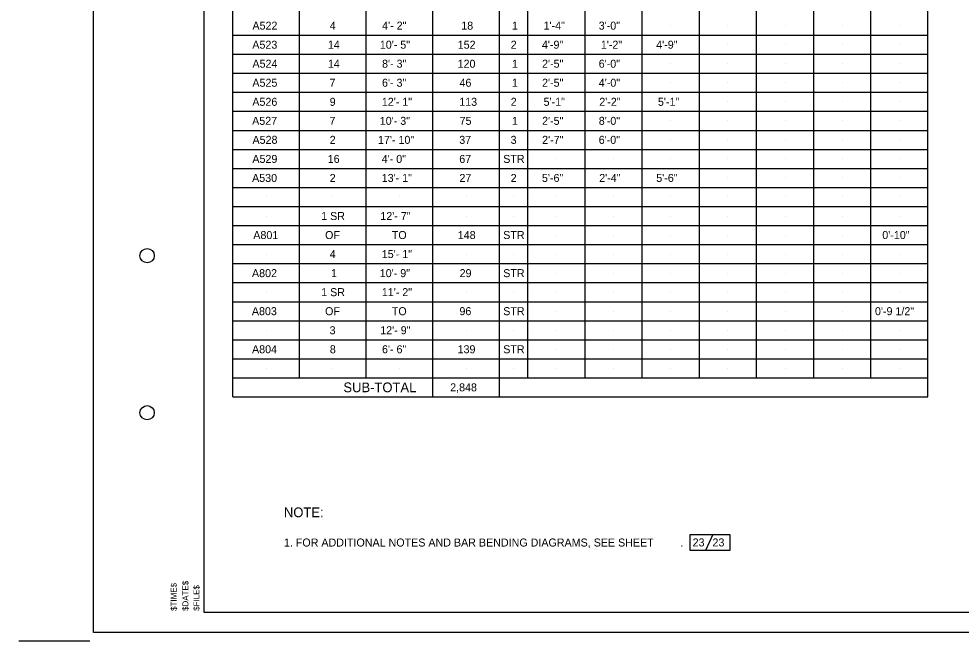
# Model space of a CAD drawing. Extents: x -9.2 to 26.7, y -0.9 to 21.1.
# Drawn here: x -9.21 to 7.28, y -0.89 to 10.01 of the extents above; entities that cross this region are included whole.
import ezdxf

# ---------------------------------------------------------------- set-up
doc = ezdxf.new("R2010")
doc.units = 0
for name, color, linetype in [('BR_P_Gen_Text', 7, 'Continuous'), ('Default', 7, 'Continuous'), ('SC_Scratch1', 7, 'Continuous'), ('SH_Border', 7, 'Continuous'), ('SH_Cut_Line', 7, 'Continuous'), ('TX_P_1', 7, 'Continuous')]:
    doc.layers.add(name, color=color, linetype=linetype)

msp = doc.modelspace()

# ---------------------------------------------------------------- linework, layer by layer
at = {"layer": 'BR_P_Gen_Text'}
for p, q in [((-5.469, 3.39), (-5.469, 20.207)), ((6.697, 3.39), (6.697, 20.207)), ((-4.302, 3.723), (-4.302, 18.39)), ((-3.135, 3.723), (-3.135, 18.39)), ((-1.969, 3.39), (-1.969, 18.39)), ((-0.802, 3.39), (-0.802, 18.39)), ((-0.302, 3.723), (-0.302, 18.39)), ((0.698, 3.723), (0.698, 18.39)), ((1.698, 3.723), (1.698, 18.39)), ((2.698, 3.723), (2.698, 18.39)), ((3.698, 3.723), (3.698, 18.39)), ((4.698, 3.723), (4.698, 18.39)), ((5.698, 3.723), (5.698, 18.39)), ((-5.469, 9.723), (6.697, 9.723)), ((-5.469, 9.39), (6.697, 9.39)), ((-5.469, 9.056), (6.697, 9.056)), ((-5.469, 8.723), (6.697, 8.723)), ((-5.469, 8.39), (6.697, 8.39)), ((-5.469, 8.056), (6.697, 8.056)), ((-5.469, 7.723), (6.697, 7.723)), ((-5.469, 7.39), (6.697, 7.39)), ((-5.469, 7.056), (6.697, 7.056)), ((-5.469, 6.723), (6.697, 6.723)), ((-5.469, 6.39), (6.697, 6.39)), ((-5.469, 6.056), (6.697, 6.056)), ((-5.469, 5.723), (6.697, 5.723)), ((-5.469, 5.39), (6.697, 5.39)), ((-5.469, 5.056), (6.697, 5.056)), ((-5.469, 4.723), (6.697, 4.723)), ((-5.469, 4.39), (6.697, 4.39)), ((-5.469, 4.056), (6.697, 4.056)), ((-5.469, 3.723), (6.697, 3.723)), ((-5.469, 3.39), (6.697, 3.39))]:
    msp.add_line(p, q, dxfattribs=at)
at = {"layer": 'SC_Scratch1'}
for p, q in [((-4.885, 9.89), (-4.885, 9.89)), ((-3.719, 9.89), (-3.719, 9.89)), ((-2.552, 9.89), (-2.552, 9.89)), ((-1.385, 9.89), (-1.385, 9.89)), ((-1.385, 9.89), (-1.385, 9.89)), ((-0.552, 9.89), (-0.552, 9.89)), ((0.198, 9.89), (0.198, 9.89)), ((1.198, 9.89), (1.198, 9.89)), ((2.198, 9.89), (2.198, 9.89)), ((3.198, 9.89), (3.198, 9.89)), ((4.198, 9.89), (4.198, 9.89)), ((5.198, 9.89), (5.198, 9.89)), ((6.198, 9.89), (6.198, 9.89)), ((6.198, 9.89), (6.198, 9.89)), ((-4.885, 9.556), (-4.885, 9.556)), ((-3.719, 9.556), (-3.719, 9.556)), ((-2.552, 9.556), (-2.552, 9.556)), ((-1.385, 9.556), (-1.385, 9.556)), ((-1.385, 9.556), (-1.385, 9.556)), ((-0.552, 9.556), (-0.552, 9.556)), ((0.198, 9.556), (0.198, 9.556)), ((1.198, 9.556), (1.198, 9.556)), ((2.198, 9.556), (2.198, 9.556)), ((3.198, 9.556), (3.198, 9.556)), ((4.198, 9.556), (4.198, 9.556)), ((5.198, 9.556), (5.198, 9.556)), ((6.198, 9.556), (6.198, 9.556)), ((6.198, 9.556), (6.198, 9.556)), ((-4.885, 9.223), (-4.885, 9.223)), ((-3.719, 9.223), (-3.719, 9.223)), ((-2.552, 9.223), (-2.552, 9.223)), ((-1.385, 9.223), (-1.385, 9.223)), ((-1.385, 9.223), (-1.385, 9.223)), ((-0.552, 9.223), (-0.552, 9.223)), ((0.198, 9.223), (0.198, 9.223)), ((1.198, 9.223), (1.198, 9.223)), ((2.198, 9.223), (2.198, 9.223)), ((3.198, 9.223), (3.198, 9.223)), ((4.198, 9.223), (4.198, 9.223)), ((5.198, 9.223), (5.198, 9.223)), ((6.198, 9.223), (6.198, 9.223)), ((6.198, 9.223), (6.198, 9.223)), ((-4.885, 8.89), (-4.885, 8.89)), ((-3.719, 8.89), (-3.719, 8.89)), ((-2.552, 8.89), (-2.552, 8.89)), ((-1.385, 8.89), (-1.385, 8.89)), ((-1.385, 8.89), (-1.385, 8.89)), ((-0.552, 8.89), (-0.552, 8.89)), ((0.198, 8.89), (0.198, 8.89)), ((1.198, 8.89), (1.198, 8.89)), ((2.198, 8.89), (2.198, 8.89)), ((3.198, 8.89), (3.198, 8.89)), ((4.198, 8.89), (4.198, 8.89)), ((5.198, 8.89), (5.198, 8.89)), ((6.198, 8.89), (6.198, 8.89)), ((6.198, 8.89), (6.198, 8.89)), ((-4.885, 8.556), (-4.885, 8.556)), ((-3.719, 8.556), (-3.719, 8.556)), ((-2.552, 8.556), (-2.552, 8.556)), ((-1.385, 8.556), (-1.385, 8.556)), ((-1.385, 8.556), (-1.385, 8.556)), ((-0.552, 8.556), (-0.552, 8.556)), ((0.198, 8.556), (0.198, 8.556)), ((1.198, 8.556), (1.198, 8.556)), ((2.198, 8.556), (2.198, 8.556)), ((3.198, 8.556), (3.198, 8.556)), ((4.198, 8.556), (4.198, 8.556)), ((5.198, 8.556), (5.198, 8.556)), ((6.198, 8.556), (6.198, 8.556)), ((6.198, 8.556), (6.198, 8.556)), ((-4.885, 8.223), (-4.885, 8.223)), ((-3.719, 8.223), (-3.719, 8.223)), ((-2.552, 8.223), (-2.552, 8.223)), ((-1.385, 8.223), (-1.385, 8.223)), ((-1.385, 8.223), (-1.385, 8.223)), ((-0.552, 8.223), (-0.552, 8.223)), ((0.198, 8.223), (0.198, 8.223)), ((1.198, 8.223), (1.198, 8.223)), ((2.198, 8.223), (2.198, 8.223)), ((3.198, 8.223), (3.198, 8.223)), ((4.198, 8.223), (4.198, 8.223)), ((5.198, 8.223), (5.198, 8.223)), ((6.198, 8.223), (6.198, 8.223)), ((-4.885, 7.89), (-4.885, 7.89)), ((-3.719, 7.89), (-3.719, 7.89)), ((-2.552, 7.89), (-2.552, 7.89)), ((-1.385, 7.89), (-1.385, 7.89)), ((-1.385, 7.89), (-1.385, 7.89)), ((-0.552, 7.89), (-0.552, 7.89)), ((0.198, 7.89), (0.198, 7.89)), ((1.198, 7.89), (1.198, 7.89)), ((2.198, 7.89), (2.198, 7.89)), ((3.198, 7.89), (3.198, 7.89)), ((4.198, 7.89), (4.198, 7.89)), ((5.197, 7.89), (5.197, 7.89)), ((6.198, 7.89), (6.198, 7.89)), ((-4.885, 7.556), (-4.885, 7.556)), ((-3.719, 7.556), (-3.719, 7.556)), ((-2.552, 7.556), (-2.552, 7.556)), ((-1.385, 7.556), (-1.385, 7.556)), ((-1.385, 7.556), (-1.385, 7.556)), ((-0.552, 7.556), (-0.552, 7.556)), ((0.198, 7.556), (0.198, 7.556)), ((1.198, 7.556), (1.198, 7.556)), ((2.198, 7.556), (2.198, 7.556)), ((3.198, 7.556), (3.198, 7.556)), ((4.198, 7.556), (4.198, 7.556)), ((5.198, 7.556), (5.198, 7.556)), ((6.198, 7.556), (6.198, 7.556)), ((-4.885, 7.223), (-4.885, 7.223)), ((-3.719, 7.223), (-3.719, 7.223)), ((-2.552, 7.223), (-2.552, 7.223)), ((-1.385, 7.223), (-1.385, 7.223)), ((-0.552, 7.223), (-0.552, 7.223)), ((0.198, 7.223), (0.198, 7.223)), ((1.198, 7.223), (1.198, 7.223)), ((2.198, 7.223), (2.198, 7.223)), ((3.198, 7.223), (3.198, 7.223)), ((4.198, 7.223), (4.198, 7.223)), ((5.198, 7.223), (5.198, 7.223)), ((6.198, 7.223), (6.198, 7.223)), ((-4.885, 6.89), (-4.885, 6.89)), ((-3.719, 6.89), (-3.719, 6.89)), ((-2.552, 6.89), (-2.552, 6.89)), ((-1.385, 6.89), (-1.385, 6.89)), ((-0.552, 6.89), (-0.552, 6.89)), ((0.198, 6.89), (0.198, 6.89)), ((1.198, 6.89), (1.198, 6.89)), ((2.198, 6.89), (2.198, 6.89)), ((3.198, 6.89), (3.198, 6.89)), ((4.198, 6.89), (4.198, 6.89)), ((5.198, 6.89), (5.198, 6.89)), ((6.198, 6.89), (6.198, 6.89)), ((-4.885, 6.556), (-4.885, 6.556)), ((-3.719, 6.556), (-3.719, 6.556)), ((-3.719, 6.556), (-3.719, 6.556)), ((-2.552, 6.556), (-2.552, 6.556)), ((-1.385, 6.556), (-1.385, 6.556)), ((-0.552, 6.556), (-0.552, 6.556)), ((0.198, 6.556), (0.198, 6.556)), ((1.198, 6.556), (1.198, 6.556)), ((2.198, 6.556), (2.198, 6.556)), ((3.198, 6.556), (3.198, 6.556)), ((4.198, 6.556), (4.198, 6.556)), ((5.198, 6.556), (5.198, 6.556)), ((6.198, 6.556), (6.198, 6.556)), ((-4.885, 6.223), (-4.885, 6.223)), ((-3.719, 6.223), (-3.719, 6.223)), ((-2.552, 6.223), (-2.552, 6.223)), ((-1.385, 6.223), (-1.385, 6.223)), ((-0.552, 6.223), (-0.552, 6.223)), ((0.198, 6.223), (0.198, 6.223)), ((1.198, 6.223), (1.198, 6.223)), ((2.198, 6.223), (2.198, 6.223)), ((3.198, 6.223), (3.198, 6.223)), ((4.198, 6.223), (4.198, 6.223)), ((5.198, 6.223), (5.198, 6.223)), ((6.198, 6.223), (6.198, 6.223)), ((-4.885, 5.89), (-4.885, 5.89)), ((-3.719, 5.89), (-3.719, 5.89)), ((-2.552, 5.89), (-2.552, 5.89)), ((-1.385, 5.89), (-1.385, 5.89)), ((-0.552, 5.89), (-0.552, 5.89)), ((0.198, 5.89), (0.198, 5.89)), ((1.198, 5.89), (1.198, 5.89)), ((2.198, 5.89), (2.198, 5.89)), ((3.198, 5.89), (3.198, 5.89)), ((4.198, 5.89), (4.198, 5.89)), ((5.198, 5.89), (5.198, 5.89)), ((6.198, 5.89), (6.198, 5.89)), ((-4.885, 5.556), (-4.885, 5.556)), ((-3.719, 5.556), (-3.719, 5.556)), ((-2.552, 5.556), (-2.552, 5.556)), ((-1.385, 5.556), (-1.385, 5.556)), ((-0.552, 5.556), (-0.552, 5.556)), ((0.198, 5.556), (0.198, 5.556)), ((1.198, 5.556), (1.198, 5.556)), ((2.198, 5.556), (2.198, 5.556)), ((3.198, 5.556), (3.198, 5.556)), ((4.198, 5.556), (4.198, 5.556)), ((5.198, 5.556), (5.198, 5.556)), ((6.198, 5.556), (6.198, 5.556)), ((-4.885, 5.223), (-4.885, 5.223)), ((-3.719, 5.223), (-3.719, 5.223)), ((-2.552, 5.223), (-2.552, 5.223)), ((-1.385, 5.223), (-1.385, 5.223)), ((-0.552, 5.223), (-0.552, 5.223)), ((0.198, 5.223), (0.198, 5.223)), ((1.198, 5.223), (1.198, 5.223)), ((2.198, 5.223), (2.198, 5.223)), ((3.198, 5.223), (3.198, 5.223)), ((4.198, 5.223), (4.198, 5.223)), ((5.198, 5.223), (5.198, 5.223)), ((6.198, 5.223), (6.198, 5.223)), ((-4.885, 4.89), (-4.885, 4.89)), ((-3.719, 4.89), (-3.719, 4.89)), ((-2.552, 4.89), (-2.552, 4.89)), ((-1.385, 4.89), (-1.385, 4.89)), ((-0.552, 4.89), (-0.552, 4.89)), ((0.198, 4.89), (0.198, 4.89)), ((1.198, 4.89), (1.198, 4.89)), ((2.198, 4.89), (2.198, 4.89)), ((3.198, 4.89), (3.198, 4.89)), ((4.198, 4.89), (4.198, 4.89)), ((5.198, 4.89), (5.198, 4.89)), ((6.198, 4.89), (6.198, 4.89)), ((-4.885, 4.556), (-4.885, 4.556)), ((-3.719, 4.556), (-3.719, 4.556)), ((-2.552, 4.556), (-2.552, 4.556)), ((-1.385, 4.556), (-1.385, 4.556)), ((-0.552, 4.556), (-0.552, 4.556)), ((0.198, 4.556), (0.198, 4.556)), ((1.198, 4.556), (1.198, 4.556)), ((2.198, 4.556), (2.198, 4.556)), ((3.198, 4.556), (3.198, 4.556)), ((4.198, 4.556), (4.198, 4.556)), ((5.198, 4.556), (5.198, 4.556)), ((6.198, 4.556), (6.198, 4.556)), ((-4.885, 4.223), (-4.885, 4.223)), ((-3.719, 4.223), (-3.719, 4.223)), ((-2.552, 4.223), (-2.552, 4.223)), ((-1.385, 4.223), (-1.385, 4.223)), ((-0.552, 4.223), (-0.552, 4.223)), ((0.198, 4.223), (0.198, 4.223)), ((1.198, 4.223), (1.198, 4.223)), ((2.198, 4.223), (2.198, 4.223)), ((3.198, 4.223), (3.198, 4.223)), ((4.198, 4.223), (4.198, 4.223)), ((5.198, 4.223), (5.198, 4.223)), ((6.198, 4.223), (6.198, 4.223)), ((-4.885, 3.89), (-4.885, 3.89)), ((-3.719, 3.89), (-3.719, 3.89)), ((-2.552, 3.89), (-2.552, 3.89)), ((-1.385, 3.89), (-1.385, 3.89)), ((-0.552, 3.89), (-0.552, 3.89)), ((0.198, 3.89), (0.198, 3.89)), ((1.198, 3.89), (1.198, 3.89)), ((2.198, 3.89), (2.198, 3.89)), ((3.198, 3.89), (3.198, 3.89)), ((4.198, 3.89), (4.198, 3.89)), ((5.198, 3.89), (5.198, 3.89)), ((6.198, 3.89), (6.198, 3.89)), ((-1.385, 3.556), (-1.385, 3.556))]:
    msp.add_line(p, q, dxfattribs=at)
at = {"layer": 'SH_Border'}
msp.add_lwpolyline([(-5.966, 20.612), (25.534, 20.612), (25.534, -0.388), (-5.966, -0.388)], close=True, dxfattribs=at)
for centre in [(-6.966, 5.862), (-6.966, 3.112)]:
    msp.add_circle(centre, 0.125, dxfattribs=at)
at = {"layer": 'SH_Cut_Line'}
msp.add_line((-7.966, -0.888), (-9.21, -0.888), dxfattribs=at)
msp.add_lwpolyline([(26.096, -0.738), (-7.904, -0.738), (-7.904, 20.912), (26.096, 20.912)], close=True, dxfattribs=at)
at = {"layer": 'TX_P_1'}
msp.add_line((2.932, 0.98), (2.804, 0.702), dxfattribs=at)
msp.add_lwpolyline([(2.535, 0.98), (3.232, 0.98), (3.232, 0.702), (2.535, 0.702)], close=True, dxfattribs=at)
msp.add_lwpolyline([(2.535, 0.98), (3.232, 0.98), (3.232, 0.702), (2.535, 0.702)], close=True, dxfattribs=at)

# ---------------------------------------------------------------- texts
at = {"layer": 'BR_P_Gen_Text'}
for s, p in [('A522', (-5.123, 9.82)), ('4', (-3.77, 9.82)), (' 4\'- 2"', (-2.906, 9.82)), ('18', (-1.469, 9.82)), ('1', (-0.581, 9.82)), ('1\'-4"', (-0.029, 9.82)), ('3\'-0"', (0.936, 9.82)), ('A523', (-5.125, 9.486)), ('14', (-3.803, 9.486)), (' 10\'- 5"', (-2.946, 9.486)), ('152', (-1.531, 9.486)), ('2', (-0.604, 9.486)), ('4\'-9"', (-0.058, 9.486)), ('1\'-2"', (0.973, 9.486)), ('4\'-9"', (1.942, 9.486)), ('A524', (-5.123, 9.153)), ('14', (-3.803, 9.153)), (' 8\'- 3"', (-2.907, 9.153)), ('120', (-1.533, 9.153)), ('1', (-0.581, 9.153)), ('2\'-5"', (-0.055, 9.153)), ('6\'-0"', (0.936, 9.153)), ('A525', (-5.124, 8.82)), ('7', (-3.775, 8.82)), (' 6\'- 3"', (-2.908, 8.82)), ('46', (-1.5, 8.82)), ('1', (-0.581, 8.82)), ('2\'-5"', (-0.055, 8.82)), ('4\'-0"', (0.937, 8.82)), ('A526', (-5.125, 8.486)), ('9', (-3.771, 8.486)), (' 12\'- 1"', (-2.911, 8.486)), ('113', (-1.505, 8.486)), ('2', (-0.604, 8.486)), ('5\'-1"', (-0.028, 8.486)), ('2\'-2"', (0.946, 8.486)), ('5\'-1"', (1.972, 8.486)), ('A527', (-5.128, 8.153)), ('7', (-3.775, 8.153)), (' 10\'- 3"', (-2.947, 8.153)), ('75', (-1.498, 8.153)), ('1', (-0.581, 8.153)), ('2\'-5"', (-0.055, 8.153)), ('8\'-0"', (0.937, 8.153)), ('A528', (-5.122, 7.82)), ('2', (-3.771, 7.82)), (' 17\'- 10"', (-2.978, 7.82)), ('37', (-1.504, 7.82)), ('3', (-0.606, 7.82)), ('2\'-7"', (-0.054, 7.82)), ('6\'-0"', (0.936, 7.82)), ('A529', (-5.124, 7.486)), ('16', (-3.806, 7.486)), (' 4\'- 0"', (-2.913, 7.486)), ('67', (-1.504, 7.486)), ('STR', (-0.735, 7.486)), ('A530', (-5.129, 7.153)), ('2', (-3.771, 7.153)), (' 13\'- 1"', (-2.913, 7.153)), ('27', (-1.501, 7.153)), ('2', (-0.604, 7.153)), ('5\'-6"', (-0.057, 7.153)), ('2\'-4"', (0.945, 7.153)), ('5\'-6"', (1.943, 7.153)), ('1 SR', (-3.92, 6.486)), (' 12\'- 7"', (-2.937, 6.486)), ('A801', (-5.108, 6.153)), ('OF', (-3.852, 6.153)), ('TO', (-2.684, 6.153)), ('148', (-1.53, 6.153)), ('STR', (-0.735, 6.153)), ('0\'-10"', (5.898, 6.153)), ('4', (-3.77, 5.82)), (' 15\'- 1"', (-2.912, 5.82)), ('A802', (-5.131, 5.486)), ('1', (-3.748, 5.486)), (' 10\'- 9"', (-2.947, 5.486)), ('29', (-1.498, 5.486)), ('STR', (-0.735, 5.486)), ('1 SR', (-3.92, 5.153)), (' 11\'- 2"', (-2.911, 5.153)), ('A803', (-5.133, 4.82)), ('OF', (-3.852, 4.82)), ('TO', (-2.684, 4.82)), ('96', (-1.501, 4.82)), ('STR', (-0.735, 4.82)), ('0\'-9 1/2"', (5.77, 4.82)), ('3', (-3.773, 4.486)), (' 12\'- 9"', (-2.939, 4.486)), ('A804', (-5.13, 4.153)), ('8', (-3.769, 4.153)), (' 6\'- 6"', (-2.908, 4.153)), ('139', (-1.533, 4.153)), ('STR', (-0.735, 4.153)), ('2,848', (-1.663, 3.486))]:
    msp.add_text(s, height=0.14, dxfattribs=at).set_placement(p)
at = {"layer": 'Default'}
for s, p in [('$DATE$', (-6.244, -0.358)), ('$TIME$', (-6.448, -0.358)), ('$FILE$', (-6.05, -0.357))]:
    msp.add_text(s, height=0.1043, rotation=90.0067, dxfattribs=at).set_placement(p)
at = {"layer": 'TX_P_1'}
msp.add_text('SUB-TOTAL', height=0.17, rotation=0.0002, dxfattribs=at).set_placement((-3.531, 3.471))
for s, height, p in [('NOTE:', 0.17, (-4.572, 1.283)), ('1. FOR ADDITIONAL NOTES AND BAR BENDING DIAGRAMS, SEE SHEET         .', 0.14, (-4.572, 0.769)), ('23', 0.14, (2.579, 0.771)), ('23', 0.14, (2.927, 0.771))]:
    msp.add_text(s, height=height, dxfattribs=at).set_placement(p)

doc.saveas('drawing.dxf')
